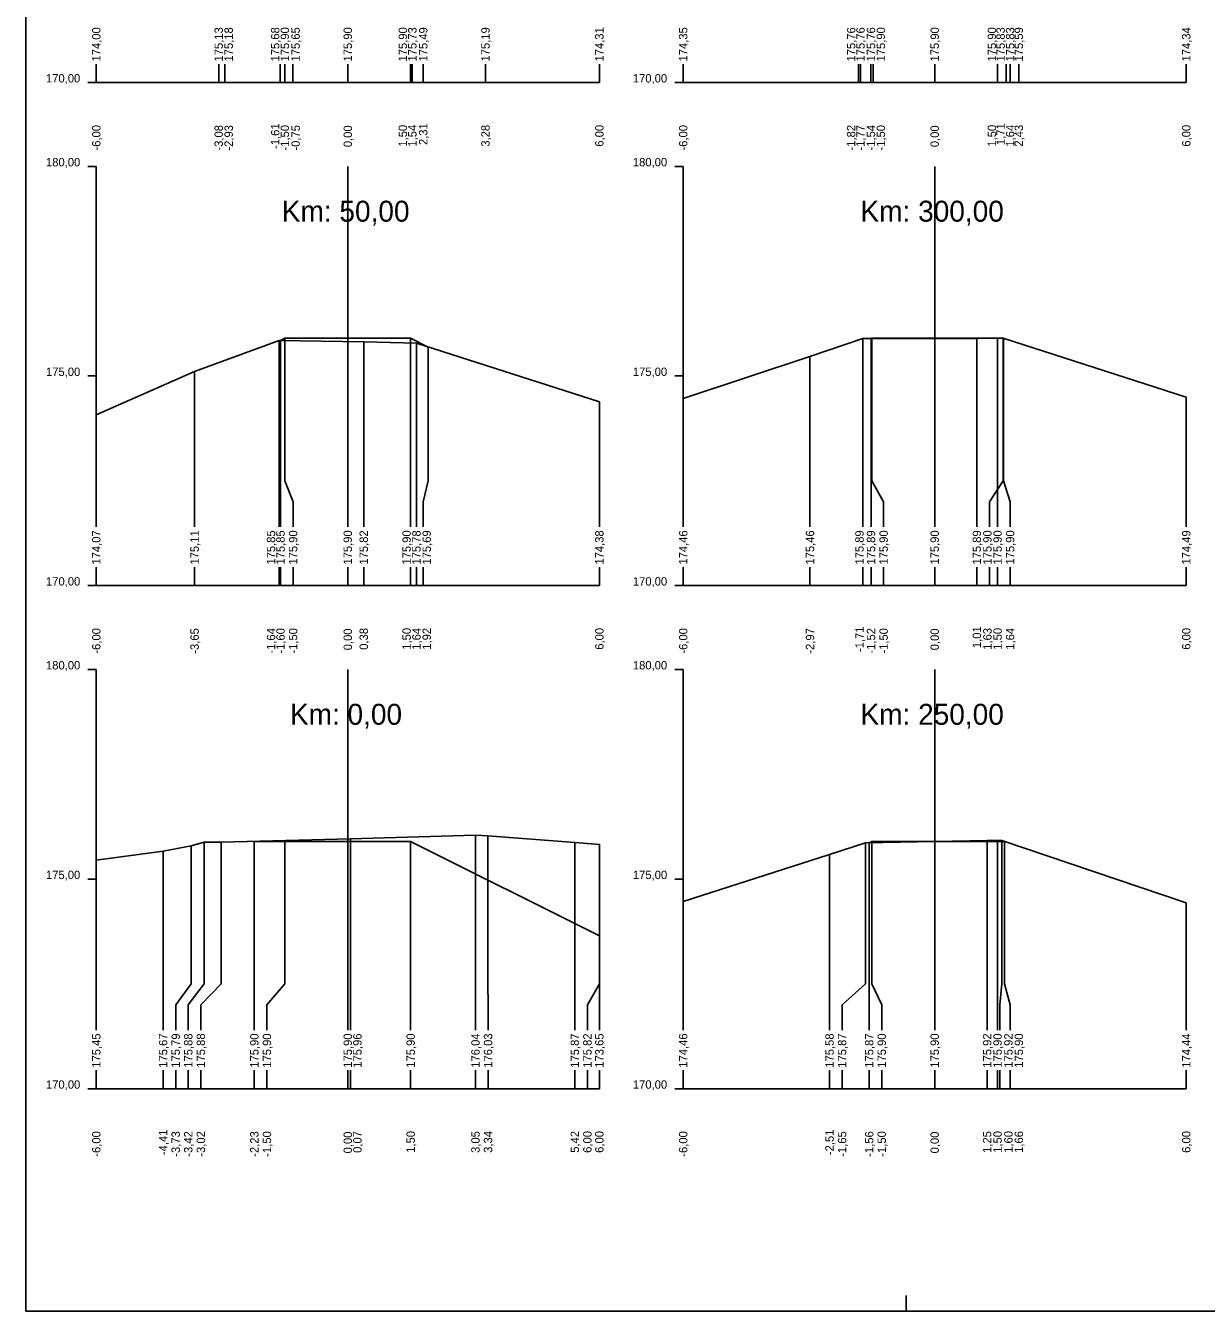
# Model space of a CAD drawing. Extents: x -614174 to -599765, y -1185887 to -1181080.
# Drawn here: x -612691.71 to -612663.55, y -1184252.54 to -1184221.88 of the extents above; entities that cross this region are included whole.
import ezdxf

# ---------------------------------------------------------------- set-up
doc = ezdxf.new("R2010")
doc.units = 0
for name, color, linetype in [('11', 7, 'Continuous'), ('16', 7, 'Continuous'), ('21', 7, 'Continuous'), ('28', 7, 'Continuous'), ('59', 7, 'Continuous'), ('8', 7, 'Continuous'), ('návrh', 7, 'Continuous')]:
    doc.layers.add(name, color=color, linetype=linetype)

msp = doc.modelspace()

# ---------------------------------------------------------------- linework, layer by layer
for points in [[(-612690.029, -1184231.164), (-612687.684, -1184230.128), (-612685.67, -1184229.386), (-612683.649, -1184229.417), (-612682.392, -1184229.454), (-612678.029, -1184230.851)], [(-612685.634, -1184229.387), (-612685.53, -1184229.335), (-612684.03, -1184229.335), (-612682.53, -1184229.335), (-612682.111, -1184229.544)], [(-612685.634, -1184229.387), (-612685.634, -1184229.387), (-612685.634, -1184229.387)], [(-612685.53, -1184229.335), (-612685.53, -1184229.335)], [(-612684.03, -1184229.335), (-612684.03, -1184229.335)], [(-612682.53, -1184229.335), (-612682.53, -1184229.335)], [(-612676.029, -1184230.773), (-612673.004, -1184229.772), (-612671.741, -1184229.344), (-612669.024, -1184229.344), (-612668.396, -1184229.331), (-612664.029, -1184230.742)], [(-612671.548, -1184229.344), (-612671.53, -1184229.335), (-612670.03, -1184229.335), (-612668.53, -1184229.335), (-612668.386, -1184229.335)], [(-612671.548, -1184229.344), (-612671.548, -1184229.344)], [(-612671.53, -1184229.335), (-612671.53, -1184229.335)], [(-612670.03, -1184229.335), (-612670.03, -1184229.335)], [(-612668.53, -1184229.335), (-612668.53, -1184229.335)], [(-612690.029, -1184241.781), (-612688.435, -1184241.567), (-612687.763, -1184241.443), (-612687.452, -1184241.352), (-612687.054, -1184241.356), (-612683.964, -1184241.272), (-612680.984, -1184241.19), (-612680.686, -1184241.202), (-612678.614, -1184241.361), (-612678.029, -1184241.409)], [(-612686.259, -1184241.335), (-612685.53, -1184241.335), (-612684.03, -1184241.335), (-612682.53, -1184241.335), (-612678.029, -1184243.585)], [(-612676.029, -1184242.769), (-612672.538, -1184241.65), (-612671.683, -1184241.367), (-612668.778, -1184241.314), (-612668.427, -1184241.314), (-612664.029, -1184242.797)], [(-612671.592, -1184241.366), (-612671.53, -1184241.335), (-612670.03, -1184241.335), (-612668.53, -1184241.335), (-612668.366, -1184241.335)], [(-612671.592, -1184241.366), (-612671.592, -1184241.366), (-612671.592, -1184241.365)], [(-612671.53, -1184241.335), (-612671.53, -1184241.335)], [(-612670.03, -1184241.335), (-612670.03, -1184241.335)], [(-612668.53, -1184241.335), (-612668.53, -1184241.335)]]:
    msp.add_lwpolyline(points)
at = {"layer": '11'}
for points in [[(-612690.029, -1184222.794), (-612690.029, -1184223.234)], [(-612687.109, -1184222.794), (-612687.109, -1184223.234)], [(-612686.964, -1184222.794), (-612686.964, -1184223.234)], [(-612685.64, -1184222.794), (-612685.64, -1184223.234)], [(-612685.53, -1184222.794), (-612685.53, -1184223.234)], [(-612685.34, -1184222.794), (-612685.34, -1184223.234)], [(-612684.03, -1184222.794), (-612684.03, -1184223.234)], [(-612682.53, -1184222.794), (-612682.53, -1184223.234)], [(-612682.49, -1184222.794), (-612682.49, -1184223.234)], [(-612682.23, -1184222.794), (-612682.23, -1184223.234)], [(-612680.746, -1184222.794), (-612680.746, -1184223.234)], [(-612678.029, -1184222.794), (-612678.029, -1184223.234)], [(-612676.029, -1184222.794), (-612676.029, -1184223.234)], [(-612671.85, -1184222.794), (-612671.85, -1184223.234)], [(-612671.8, -1184222.794), (-612671.8, -1184223.234)], [(-612671.55, -1184222.794), (-612671.55, -1184223.234)], [(-612671.5, -1184222.794), (-612671.5, -1184223.234)], [(-612670.03, -1184222.794), (-612670.03, -1184223.234)], [(-612668.53, -1184222.794), (-612668.53, -1184223.234)], [(-612668.323, -1184222.794), (-612668.323, -1184223.234)], [(-612668.23, -1184222.794), (-612668.23, -1184223.234)], [(-612668.023, -1184222.794), (-612668.023, -1184223.234)], [(-612664.029, -1184222.794), (-612664.029, -1184223.234)], [(-612685.67, -1184229.386), (-612685.67, -1184232.734), (-612685.67, -1184233.234), (-612685.67, -1184233.835)], [(-612685.634, -1184229.387), (-612685.634, -1184232.734), (-612685.634, -1184233.234), (-612685.634, -1184233.835)], [(-612685.53, -1184229.335), (-612685.53, -1184232.734), (-612685.334, -1184233.234), (-612685.334, -1184233.835)], [(-612684.03, -1184229.335), (-612684.03, -1184232.734), (-612684.03, -1184233.234), (-612684.03, -1184233.835)], [(-612683.649, -1184229.417), (-612683.649, -1184232.734), (-612683.649, -1184233.234), (-612683.649, -1184233.835)], [(-612682.53, -1184229.335), (-612682.53, -1184232.734), (-612682.53, -1184233.234), (-612682.53, -1184233.835)], [(-612682.392, -1184229.454), (-612682.392, -1184232.734), (-612682.392, -1184233.234), (-612682.392, -1184233.835)], [(-612682.111, -1184229.544), (-612682.111, -1184232.734), (-612682.23, -1184233.234), (-612682.23, -1184233.835)], [(-612671.741, -1184229.344), (-612671.741, -1184232.734), (-612671.741, -1184233.234), (-612671.741, -1184233.835)], [(-612671.548, -1184229.344), (-612671.548, -1184232.734), (-612671.548, -1184233.234), (-612671.548, -1184233.835)], [(-612671.53, -1184229.335), (-612671.53, -1184232.734), (-612671.248, -1184233.234), (-612671.248, -1184233.835)], [(-612670.03, -1184229.335), (-612670.03, -1184232.734), (-612670.03, -1184233.234), (-612670.03, -1184233.835)], [(-612669.024, -1184229.344), (-612669.024, -1184232.734), (-612669.024, -1184233.234), (-612669.024, -1184233.835)], [(-612668.396, -1184229.331), (-612668.396, -1184232.734), (-612668.724, -1184233.234), (-612668.724, -1184233.835)], [(-612668.53, -1184229.335), (-612668.53, -1184232.734), (-612668.53, -1184233.234), (-612668.53, -1184233.835)], [(-612668.386, -1184229.335), (-612668.386, -1184232.734), (-612668.23, -1184233.234), (-612668.23, -1184233.835)], [(-612673.004, -1184229.772), (-612673.004, -1184232.734), (-612673.004, -1184233.234), (-612673.004, -1184233.835)], [(-612687.684, -1184230.128), (-612687.684, -1184232.734), (-612687.684, -1184233.234), (-612687.684, -1184233.835)], [(-612676.029, -1184230.773), (-612676.029, -1184232.734), (-612676.029, -1184233.234), (-612676.029, -1184233.835)], [(-612664.029, -1184230.742), (-612664.029, -1184232.734), (-612664.029, -1184233.234), (-612664.029, -1184233.835)], [(-612678.029, -1184230.851), (-612678.029, -1184232.734), (-612678.029, -1184233.234), (-612678.029, -1184233.835)], [(-612690.029, -1184231.164), (-612690.029, -1184232.734), (-612690.029, -1184233.234), (-612690.029, -1184233.835)], [(-612690.029, -1184234.794), (-612690.029, -1184235.234)], [(-612687.684, -1184234.794), (-612687.684, -1184235.234)], [(-612685.67, -1184234.794), (-612685.67, -1184235.234)], [(-612685.634, -1184234.794), (-612685.634, -1184235.234)], [(-612685.334, -1184234.794), (-612685.334, -1184235.234)], [(-612684.03, -1184234.794), (-612684.03, -1184235.234)], [(-612683.649, -1184234.794), (-612683.649, -1184235.234)], [(-612682.53, -1184234.794), (-612682.53, -1184235.234)], [(-612682.392, -1184234.794), (-612682.392, -1184235.234)], [(-612682.23, -1184234.794), (-612682.23, -1184235.234)], [(-612678.029, -1184234.794), (-612678.029, -1184235.234)], [(-612676.029, -1184234.794), (-612676.029, -1184235.234)], [(-612673.004, -1184234.794), (-612673.004, -1184235.234)], [(-612671.741, -1184234.794), (-612671.741, -1184235.234)], [(-612671.548, -1184234.794), (-612671.548, -1184235.234)], [(-612671.248, -1184234.794), (-612671.248, -1184235.234)], [(-612670.03, -1184234.794), (-612670.03, -1184235.234)], [(-612669.024, -1184234.794), (-612669.024, -1184235.234)], [(-612668.724, -1184234.794), (-612668.724, -1184235.234)], [(-612668.53, -1184234.794), (-612668.53, -1184235.234)], [(-612668.23, -1184234.794), (-612668.23, -1184235.234)], [(-612664.029, -1184234.794), (-612664.029, -1184235.234)], [(-612680.984, -1184241.19), (-612680.984, -1184244.734), (-612680.984, -1184245.234), (-612680.984, -1184245.835)], [(-612680.686, -1184241.202), (-612680.686, -1184244.734), (-612680.684, -1184245.234), (-612680.684, -1184245.835)], [(-612688.435, -1184241.567), (-612688.435, -1184244.734), (-612688.435, -1184245.234), (-612688.435, -1184245.835)], [(-612687.763, -1184241.443), (-612687.763, -1184244.734), (-612688.135, -1184245.234), (-612688.135, -1184245.835)], [(-612687.452, -1184241.352), (-612687.452, -1184244.734), (-612687.835, -1184245.234), (-612687.835, -1184245.835)], [(-612687.054, -1184241.356), (-612687.054, -1184244.734), (-612687.535, -1184245.234), (-612687.535, -1184245.835)], [(-612686.259, -1184241.335), (-612686.259, -1184244.734), (-612686.259, -1184245.234), (-612686.259, -1184245.835)], [(-612685.53, -1184241.335), (-612685.53, -1184244.734), (-612685.959, -1184245.234), (-612685.959, -1184245.835)], [(-612684.03, -1184241.335), (-612684.03, -1184244.734), (-612684.03, -1184245.234), (-612684.03, -1184245.835)], [(-612683.964, -1184241.272), (-612683.964, -1184244.734), (-612683.964, -1184245.234), (-612683.964, -1184245.835)], [(-612682.53, -1184241.335), (-612682.53, -1184244.734), (-612682.53, -1184245.234), (-612682.53, -1184245.835)], [(-612678.614, -1184241.361), (-612678.614, -1184244.734), (-612678.614, -1184245.234), (-612678.614, -1184245.835)], [(-612678.029, -1184241.409), (-612678.029, -1184244.734), (-612678.314, -1184245.234), (-612678.314, -1184245.835)], [(-612671.683, -1184241.367), (-612671.683, -1184244.734), (-612672.238, -1184245.234), (-612672.238, -1184245.835)], [(-612671.592, -1184241.366), (-612671.592, -1184244.734), (-612671.592, -1184245.234), (-612671.592, -1184245.835)], [(-612671.53, -1184241.335), (-612671.53, -1184244.734), (-612671.292, -1184245.234), (-612671.292, -1184245.835)], [(-612670.03, -1184241.335), (-612670.03, -1184244.734), (-612670.03, -1184245.234), (-612670.03, -1184245.835)], [(-612668.778, -1184241.314), (-612668.778, -1184244.734), (-612668.778, -1184245.234), (-612668.778, -1184245.835)], [(-612668.53, -1184241.335), (-612668.53, -1184244.734), (-612668.53, -1184245.234), (-612668.53, -1184245.835)], [(-612668.427, -1184241.314), (-612668.427, -1184244.734), (-612668.478, -1184245.234), (-612668.478, -1184245.835)], [(-612668.366, -1184241.335), (-612668.366, -1184244.734), (-612668.23, -1184245.234), (-612668.23, -1184245.835)], [(-612690.029, -1184241.781), (-612690.029, -1184244.734), (-612690.029, -1184245.234), (-612690.029, -1184245.835)], [(-612672.538, -1184241.65), (-612672.538, -1184244.734), (-612672.538, -1184245.234), (-612672.538, -1184245.835)], [(-612676.029, -1184242.769), (-612676.029, -1184244.734), (-612676.029, -1184245.234), (-612676.029, -1184245.835)], [(-612664.029, -1184242.797), (-612664.029, -1184244.734), (-612664.029, -1184245.234), (-612664.029, -1184245.835)], [(-612678.029, -1184243.585), (-612678.029, -1184244.734), (-612678.029, -1184245.234), (-612678.029, -1184245.835)], [(-612690.029, -1184246.794), (-612690.029, -1184247.234)], [(-612688.435, -1184246.794), (-612688.435, -1184247.234)], [(-612688.135, -1184246.794), (-612688.135, -1184247.234)], [(-612687.835, -1184246.794), (-612687.835, -1184247.234)], [(-612687.535, -1184246.794), (-612687.535, -1184247.234)], [(-612686.259, -1184246.794), (-612686.259, -1184247.234)], [(-612685.959, -1184246.794), (-612685.959, -1184247.234)], [(-612684.03, -1184246.794), (-612684.03, -1184247.234)], [(-612683.964, -1184246.794), (-612683.964, -1184247.234)], [(-612682.53, -1184246.794), (-612682.53, -1184247.234)], [(-612680.984, -1184246.794), (-612680.984, -1184247.234)], [(-612680.684, -1184246.794), (-612680.684, -1184247.234)], [(-612678.614, -1184246.794), (-612678.614, -1184247.234)], [(-612678.314, -1184246.794), (-612678.314, -1184247.234)], [(-612678.029, -1184246.794), (-612678.029, -1184247.234)], [(-612676.029, -1184246.794), (-612676.029, -1184247.234)], [(-612672.538, -1184246.794), (-612672.538, -1184247.234)], [(-612672.238, -1184246.794), (-612672.238, -1184247.234)], [(-612671.592, -1184246.794), (-612671.592, -1184247.234)], [(-612671.292, -1184246.794), (-612671.292, -1184247.234)], [(-612670.03, -1184246.794), (-612670.03, -1184247.234)], [(-612668.778, -1184246.794), (-612668.778, -1184247.234)], [(-612668.53, -1184246.794), (-612668.53, -1184247.234)], [(-612668.478, -1184246.794), (-612668.478, -1184247.234)], [(-612668.23, -1184246.794), (-612668.23, -1184247.234)], [(-612664.029, -1184246.794), (-612664.029, -1184247.234)]]:
    msp.add_lwpolyline(points, dxfattribs=at)
at = {"layer": '16'}
for p, q in [((-612690.029, -1184223.234), (-612678.029, -1184223.234)), ((-612676.029, -1184223.234), (-612664.029, -1184223.234)), ((-612690.029, -1184235.234), (-612678.029, -1184235.234)), ((-612676.029, -1184235.234), (-612664.029, -1184235.234)), ((-612690.029, -1184247.234), (-612678.029, -1184247.234)), ((-612676.029, -1184247.234), (-612664.029, -1184247.234))]:
    msp.add_line(p, q, dxfattribs=at)
for points in [[(-612682.112, -1184229.544), (-612682.111, -1184229.544), (-612682.111, -1184229.544)], [(-612668.386, -1184229.335), (-612668.386, -1184229.335), (-612668.386, -1184229.335)], [(-612668.366, -1184241.335), (-612668.366, -1184241.335), (-612668.366, -1184241.335)]]:
    msp.add_lwpolyline(points, dxfattribs=at)
at = {"layer": '21'}
for p, q in [((-612690.229, -1184223.234), (-612690.029, -1184223.234)), ((-612676.229, -1184223.234), (-612676.029, -1184223.234)), ((-612690.229, -1184225.234), (-612690.029, -1184225.234)), ((-612676.229, -1184225.234), (-612676.029, -1184225.234)), ((-612690.229, -1184230.234), (-612690.029, -1184230.234)), ((-612676.229, -1184230.234), (-612676.029, -1184230.234)), ((-612690.229, -1184235.234), (-612690.029, -1184235.234)), ((-612676.229, -1184235.234), (-612676.029, -1184235.234)), ((-612690.229, -1184237.234), (-612690.029, -1184237.234)), ((-612676.229, -1184237.234), (-612676.029, -1184237.234)), ((-612690.229, -1184242.234), (-612690.029, -1184242.234)), ((-612676.229, -1184242.234), (-612676.029, -1184242.234)), ((-612690.229, -1184247.234), (-612690.029, -1184247.234)), ((-612676.229, -1184247.234), (-612676.029, -1184247.234))]:
    msp.add_line(p, q, dxfattribs=at)
at = {"layer": '28'}
for p, q in [((-612684.029, -1184223.234), (-612684.029, -1184222.794)), ((-612670.029, -1184223.234), (-612670.029, -1184222.794)), ((-612684.029, -1184233.835), (-612684.029, -1184225.234)), ((-612670.029, -1184233.835), (-612670.029, -1184225.234)), ((-612684.029, -1184235.234), (-612684.029, -1184234.794)), ((-612670.029, -1184235.234), (-612670.029, -1184234.794)), ((-612684.029, -1184245.835), (-612684.029, -1184237.234)), ((-612670.029, -1184245.835), (-612670.029, -1184237.234)), ((-612684.029, -1184247.234), (-612684.029, -1184246.794)), ((-612670.029, -1184247.234), (-612670.029, -1184246.794))]:
    msp.add_line(p, q, dxfattribs=at)
at = {"layer": '8'}
for p, q in [((-612690.029, -1184223.234), (-612690.029, -1184222.794)), ((-612676.029, -1184223.234), (-612676.029, -1184222.794)), ((-612690.029, -1184233.835), (-612690.029, -1184225.234)), ((-612676.029, -1184233.835), (-612676.029, -1184225.234)), ((-612690.029, -1184235.234), (-612690.029, -1184234.794)), ((-612676.029, -1184235.234), (-612676.029, -1184234.794)), ((-612690.029, -1184245.835), (-612690.029, -1184237.234)), ((-612676.029, -1184245.835), (-612676.029, -1184237.234)), ((-612690.029, -1184247.234), (-612690.029, -1184246.794)), ((-612676.029, -1184247.234), (-612676.029, -1184246.794))]:
    msp.add_line(p, q, dxfattribs=at)
at = {"layer": 'návrh'}
for p, q in [((-612691.713, -1184252.543), (-612691.713, -1184186.724)), ((-612670.713, -1184252.543), (-612670.713, -1184252.163)), ((-612691.713, -1184252.543), (-612670.713, -1184252.543)), ((-612670.713, -1184252.543), (-612649.713, -1184252.543))]:
    msp.add_line(p, q, dxfattribs=at)

# ---------------------------------------------------------------- texts
for p in [(-612671.549, -1184229.344), (-612686.259, -1184241.335)]:
    msp.add_text('+', height=0.001).set_placement(p)
at = {"layer": '16'}
for s, p in [('174,00', (-612689.929, -1184222.734)), ('175,13', (-612687.009, -1184222.734)), ('175,18', (-612686.771, -1184222.734)), ('175,68', (-612685.661, -1184222.734)), ('175,90', (-612685.43, -1184222.734)), ('175,65', (-612685.175, -1184222.734)), ('175,90', (-612683.93, -1184222.734)), ('175,90', (-612682.617, -1184222.734)), ('175,73', (-612682.39, -1184222.734)), ('175,49', (-612682.13, -1184222.734)), ('175,19', (-612680.646, -1184222.734)), ('174,31', (-612677.929, -1184222.734)), ('174,35', (-612675.929, -1184222.734)), ('175,76', (-612671.923, -1184222.734)), ('175,76', (-612671.7, -1184222.734)), ('175,76', (-612671.45, -1184222.734)), ('175,90', (-612671.213, -1184222.734)), ('175,90', (-612669.93, -1184222.734)), ('175,90', (-612668.565, -1184222.734)), ('175,83', (-612668.358, -1184222.734)), ('175,83', (-612668.13, -1184222.734)), ('175,59', (-612667.923, -1184222.734)), ('174,34', (-612663.929, -1184222.734)), ('174,07', (-612689.929, -1184234.734)), ('175,11', (-612687.584, -1184234.734)), ('175,85', (-612685.76, -1184234.734)), ('175,85', (-612685.534, -1184234.734)), ('175,90', (-612685.234, -1184234.734)), ('175,90', (-612683.93, -1184234.734)), ('175,82', (-612683.549, -1184234.734)), ('175,90', (-612682.527, -1184234.734)), ('175,78', (-612682.292, -1184234.734)), ('175,69', (-612682.047, -1184234.734)), ('174,38', (-612677.929, -1184234.734)), ('174,46', (-612675.929, -1184234.734)), ('175,46', (-612672.904, -1184234.734)), ('175,89', (-612671.724, -1184234.734)), ('175,89', (-612671.448, -1184234.734)), ('175,90', (-612671.148, -1184234.734)), ('175,90', (-612669.93, -1184234.734)), ('175,89', (-612668.924, -1184234.734)), ('175,90', (-612668.672, -1184234.734)), ('175,90', (-612668.43, -1184234.734)), ('175,90', (-612668.13, -1184234.734)), ('174,49', (-612663.929, -1184234.734)), ('175,45', (-612689.929, -1184246.734)), ('175,67', (-612688.335, -1184246.734)), ('175,79', (-612688.035, -1184246.734)), ('175,88', (-612687.735, -1184246.734)), ('175,88', (-612687.435, -1184246.734)), ('175,90', (-612686.159, -1184246.734)), ('175,90', (-612685.859, -1184246.734)), ('175,90', (-612683.93, -1184246.734)), ('175,96', (-612683.701, -1184246.734)), ('175,90', (-612682.43, -1184246.734)), ('176,04', (-612680.884, -1184246.734)), ('176,03', (-612680.584, -1184246.734)), ('175,87', (-612678.514, -1184246.734)), ('175,82', (-612678.214, -1184246.734)), ('173,65', (-612677.929, -1184246.734)), ('174,46', (-612675.929, -1184246.734)), ('175,58', (-612672.438, -1184246.734)), ('175,87', (-612672.138, -1184246.734)), ('175,87', (-612671.492, -1184246.734)), ('175,90', (-612671.192, -1184246.734)), ('175,90', (-612669.93, -1184246.734)), ('175,92', (-612668.678, -1184246.734)), ('175,90', (-612668.43, -1184246.734)), ('175,92', (-612668.171, -1184246.734)), ('175,90', (-612667.922, -1184246.734)), ('174,44', (-612663.929, -1184246.734))]:
    msp.add_text(s, height=0.2, rotation=90, dxfattribs=at).set_placement(p)
at = {"layer": '21'}
for s, p in [('170,00', (-612691.229, -1184223.234)), ('170,00', (-612677.229, -1184223.234)), ('180,00', (-612691.229, -1184225.234)), ('180,00', (-612677.229, -1184225.234)), ('175,00', (-612691.229, -1184230.234)), ('175,00', (-612677.229, -1184230.234)), ('170,00', (-612691.229, -1184235.234)), ('170,00', (-612677.229, -1184235.234)), ('180,00', (-612691.229, -1184237.234)), ('180,00', (-612677.229, -1184237.234)), ('175,00', (-612691.229, -1184242.234)), ('175,00', (-612677.229, -1184242.234)), ('170,00', (-612691.229, -1184247.234)), ('170,00', (-612677.229, -1184247.234))]:
    msp.add_text(s, height=0.2, dxfattribs=at).set_placement(p)
at = {"layer": '28'}
for s, p in [('Km: 50,00', (-612685.604, -1184226.554)), ('Km: 300,00', (-612671.799, -1184226.554)), ('Km: 0,00', (-612685.41, -1184238.554)), ('Km: 250,00', (-612671.799, -1184238.554))]:
    msp.add_text(s, height=0.5, dxfattribs=at).set_placement(p)
at = {"layer": '59'}
for s, p in [('-6,00', (-612689.929, -1184224.857)), ('-3,08', (-612687.009, -1184224.858)), ('-2,93', (-612686.771, -1184224.858)), ('-1,61', (-612685.661, -1184224.819)), ('-1,50', (-612685.43, -1184224.857)), ('-0,75', (-612685.175, -1184224.859)), ('0,00', (-612683.93, -1184224.777)), ('1,50', (-612682.617, -1184224.764)), ('1,54', (-612682.39, -1184224.764)), ('2,31', (-612682.13, -1184224.726)), ('3,28', (-612680.646, -1184224.765)), ('6,00', (-612677.929, -1184224.764)), ('-6,00', (-612675.929, -1184224.857)), ('-1,82', (-612671.923, -1184224.856)), ('-1,77', (-612671.7, -1184224.858)), ('-1,54', (-612671.45, -1184224.857)), ('-1,50', (-612671.213, -1184224.857)), ('0,00', (-612669.93, -1184224.777)), ('1,50', (-612668.565, -1184224.764)), ('1,71', (-612668.358, -1184224.726)), ('1,64', (-612668.13, -1184224.764)), ('2,43', (-612667.923, -1184224.765)), ('6,00', (-612663.929, -1184224.764)), ('-6,00', (-612689.929, -1184236.857)), ('-3,65', (-612687.584, -1184236.859)), ('-1,64', (-612685.76, -1184236.857)), ('-1,60', (-612685.534, -1184236.857)), ('-1,50', (-612685.234, -1184236.857)), ('0,00', (-612683.93, -1184236.777)), ('0,38', (-612683.549, -1184236.765)), ('1,50', (-612682.527, -1184236.764)), ('1,64', (-612682.292, -1184236.764)), ('1,92', (-612682.047, -1184236.763)), ('6,00', (-612677.929, -1184236.764)), ('-6,00', (-612675.929, -1184236.857)), ('-2,97', (-612672.904, -1184236.858)), ('-1,71', (-612671.724, -1184236.819)), ('-1,52', (-612671.448, -1184236.856)), ('-1,50', (-612671.148, -1184236.857)), ('0,00', (-612669.93, -1184236.777)), ('1,01', (-612668.924, -1184236.726)), ('1,63', (-612668.672, -1184236.765)), ('1,50', (-612668.43, -1184236.764)), ('1,64', (-612668.13, -1184236.764)), ('6,00', (-612663.929, -1184236.764)), ('-6,00', (-612689.929, -1184248.857)), ('-4,41', (-612688.335, -1184248.819)), ('-3,73', (-612688.035, -1184248.858)), ('-3,42', (-612687.735, -1184248.856)), ('-3,02', (-612687.435, -1184248.856)), ('-2,23', (-612686.159, -1184248.858)), ('-1,50', (-612685.859, -1184248.857)), ('0,00', (-612683.93, -1184248.777)), ('0,07', (-612683.701, -1184248.765)), ('1,50', (-612682.43, -1184248.764)), ('3,05', (-612680.884, -1184248.766)), ('3,34', (-612680.584, -1184248.764)), ('5,42', (-612678.514, -1184248.763)), ('6,00', (-612678.214, -1184248.764)), ('6,00', (-612677.929, -1184248.764)), ('-6,00', (-612675.929, -1184248.857)), ('-2,51', (-612672.438, -1184248.819)), ('-1,65', (-612672.138, -1184248.859)), ('-1,56', (-612671.492, -1184248.858)), ('-1,50', (-612671.192, -1184248.857)), ('0,00', (-612669.93, -1184248.777)), ('1,25', (-612668.678, -1184248.766)), ('1,50', (-612668.43, -1184248.764)), ('1,60', (-612668.171, -1184248.764)), ('1,66', (-612667.922, -1184248.765)), ('6,00', (-612663.929, -1184248.764))]:
    msp.add_text(s, height=0.2, rotation=90, dxfattribs=at).set_placement(p)

doc.saveas('drawing.dxf')
